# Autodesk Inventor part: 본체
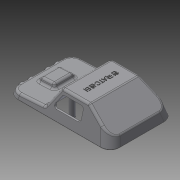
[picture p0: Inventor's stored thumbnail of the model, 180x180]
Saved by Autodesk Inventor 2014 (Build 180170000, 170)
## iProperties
Created: 2015-05
Part Number: 본체
Material: 일반
Document SubType Name: Modeling
Designer: 학생용
Density: 1 g/cm^3
Appearance: 기본값
Author: 학생용
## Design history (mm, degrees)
sketch "스케치1"
  geometry: L1 (0, 0)-(-122, 0); L2 (-122, 0)-(-120.392, 6); L3 (-120.392, 6)-(-80, 8.117); L4 (-80, 8.117)-(-65.701, 31); L5 (-65.701, 31)-(-32.947, 31); L6 (-32.947, 31)-(-2.947, 11); L7 (-2.947, 11)-(0, 0); 1 further point
  constraints: 14 end point, 2 horizontal, 1 coincident
  dimensions: "d0" = 122 distance of L1.start L1.end; "d1" = 105 deg angle of L2 L1; "d2" = 105 deg angle of L1 L7; "d3" = 125 deg angle of L4 L3; "d4" = 6 vertical distance of L1.end L2.end; "d5" = 31 distance from line of L1 L5.end; "d6" = 30 horizontal distance of L6.end L5.end; "d7" = 42 horizontal distance of L1.end L3.end; "d8" = 20 vertical distance of L6.end L5.end; "d9" = 3 deg angle of L1 L3
extrude "돌출1" new body sketch "스케치1" distance "d10" = 76; taper "d11" = 0 deg
node "작업 평면1"
sketch "스케치3"
  geometry: L1 (0, 0)-(6, 0) reference; L2 (6, 0)-(6, -76) reference; L3 (0, -76)-(6, -76) reference; L4 (0, 0)-(0, -76) reference; L5 (37.372, -76)-(37.372, -65.986); L6 (37.372, -65.986)-(0, -76); L7 (0, -76)-(37.372, -76); L8 (0, 0)-(37.372, -10.014); L9 (0, 0)-(37.372, 0); L10 (37.372, 0)-(37.372, -10.014); 1 further point
  constraints: 12 end point, 2 horizontal, 1 coincident, 1 parallel, 1 vertical, 1 vertical alignment
  dimensions: "d15" = 105 deg angle of L4 L8; "d16" = 105 deg angle of L6 L4; "d17" = 31.37205 distance between parallel lines of L5 L2
extrude "돌출2" cut sketch "스케치3" stored distance "d18" = 76; taper "d19" = 0 deg
sketch "스케치4"
  geometry: L1 (0, 0)-(0, 72.785) reference; L2 (9.08, 49.392)-(29.08, 49.392); L3 (29.08, 49.392)-(29.08, 23.392); L4 (29.08, 23.392)-(9.08, 23.392); L5 (9.08, 23.392)-(9.08, 49.392); L6 (9.08, 49.392)-(29.08, 23.392); L7 (29.08, 49.392)-(9.08, 23.392); L8 (-1.92, -1.608)-(-1.92, 74.392) reference; 4 further points
  constraints: 12 end point, 4 midpoint, 2 parallel, 1 horizontal, 1 horizontal alignment, 1 perpendicular
  dimensions: "d20" = 20 distance of L2.start L2.end; "d21" = 26 distance of L2.end L3.end; "d22" = 11 distance between parallel lines of L5 L8
extrude "돌출3" join sketch "스케치4" distance "d23" = 5; taper "d24" = -20 deg
fillet "모깎기1" dims "d25" = 12
fillet "모깎기2" dims "d26" = 12
feature "쉘1" dims "d28" = 2
node "작업 평면2"
sketch "스케치5"
  geometry: L1 (-72.303, 11)-(-38.303, 11); L2 (-38.303, 11)-(-38.303, 26); L3 (-38.303, 26)-(-62.929, 26); L4 (-62.929, 26)-(-72.303, 11); L5 (-33.856, 31)-(-64.038, 31) reference; L6 (-66.582, 29.59)-(-79.172, 9.441) reference; L7 (-14.472, 18.683)-(-32.192, 30.496) reference; 1 further point
  constraints: 8 end point, 2 horizontal, 1 parallel, 1 vertical
  dimensions: "d32" = 34 distance of L1.start L1.end; "d33" = 15 distance between parallel lines of L1 L3; "d34" = 5 distance between parallel lines of L3 L5; "d36" = 5 distance from line of L6 L3.end
extrude "돌출4" cut sketch "스케치5" stored distance "d40" = 5; taper "d41" = 0 deg
fillet "모깎기4" dims "d42" = 3
sketch "스케치8" dims "d55" = 6
  geometry: L1 (12.179, 38.008)-(12.179, 14.809) reference; L2 (12.179, 38.008)-(12.179, 26.409); L3 (29.355, 14.809)-(29.355, 38.008) reference; L4 (12.179, 26.409)-(29.355, 26.409); L5 (100.767, 23.409)-(124.378, 23.409); L6 (29.355, 26.409)-(20.767, 26.409); C1 r 3 at (20.767, 26.409); C2 r 3 at (60.767, 4.409); C3 r 3 at (60.767, 48.409); 4 further points
  constraints: 8 end point, 5 midpoint, 3 centre point, 3 horizontal, 2 vertical alignment, 1 coincident, 1 horizontal alignment, 1 vertical, 2 other
  dimensions: "d52" = 6 diameter of C1; "d53" = 6 diameter of C2; "d54" = 6 diameter of C3; "d57" = 11.5995 distance of L1.start L2.end; "d58" = 8.588 distance of L6.start L6.end; "d59" = 80 distance of point (100.767, 26.409) C1.centre; "d60" = 40 horizontal distance of C2.centre L6.end; "d61" = 22 vertical distance of C2.centre L6.end; "d62" = 44 distance of C2.centre C3.centre
fillet "모깎기5" dims "d56" = 3
extrude "돌출5" join sketch "스케치8" stored distance "d63" = 5; taper "d64" = 0 deg
node "작업 평면3"
sketch "스케치9"
  geometry: L1 (-109.821, 4.551)-(-118.837, 4.079) reference; L2 (-118.837, 4.079)-(-119.929, 0) reference; L3 (-119.929, 0)-(-122, 0) reference; L4 (-122, 0)-(-120.956, 3.895) reference; L5 (-118.216, 6.114)-(-113.422, 6.365) reference; L6 (-110.71, 8.484)-(-110.383, 9.555) reference; L7 (-107.671, 11.674)-(-95.528, 12.31) reference; L8 (-92.61, 10.486)-(-92.172, 9.456) reference; L9 (-89.254, 7.632)-(-81.56, 8.035) reference; L10 (-79.172, 9.441)-(-66.582, 29.59) reference; L11 (-64.038, 31)-(-33.856, 31) reference; L12 (-32.192, 30.496)-(-3.888, 11.627) reference; L13 (-2.655, 9.908)-(0, 0) reference; L14 (0, 0)-(-2.071, 0) reference; L15 (-2.071, 0)-(-4.684, 9.754) reference; L16 (-4.684, 9.754)-(-18.233, 18.787) reference; L17 (-18.233, 18.787)-(-18.233, 0) reference; L18 (-18.233, 0)-(-24.233, 0) reference; L19 (-24.233, 0)-(-24.233, 22.787) reference; L20 (-24.233, 22.787)-(-33.553, 29) reference; L21 (-33.553, 29)-(-64.592, 29) reference; L22 (-64.592, 29)-(-78.856, 6.174) reference; L23 (-78.856, 6.174)-(-92.645, 5.451) reference; L24 (-92.645, 5.451)-(-94.725, 10.349) reference; L25 (-94.725, 10.349)-(-98.233, 10.165) reference; L26 (-98.233, 10.165)-(-98.233, 0) reference; L27 (-98.233, 0)-(-104.233, 0) reference; L28 (-104.233, 0)-(-104.233, 9.851) reference; L29 (-104.233, 9.851)-(-108.265, 9.64) reference; L30 (-108.265, 9.64)-(-109.821, 4.551) reference; L31 (-106.233, 2)-(-96.233, 2); L32 (-107.587, 9.675)-(-106.233, 2); L33 (-94.761, 10.347)-(-96.233, 2); L34 (-107.587, 9.675)-(-104.233, 9.851); L35 (-94.725, 10.349)-(-107.587, 9.675); L36 (-26.233, 2)-(-16.233, 2); A1 r 3 centre (-118.059, 3.118) between (-118.216, 6.114) and (-120.956, 3.895) reference; A2 r 3 centre (-113.579, 9.361) between (-113.422, 6.365) and (-110.71, 8.484) reference; A3 r 3 centre (-107.514, 8.678) between (-107.671, 11.674) and (-110.383, 9.555) reference; A4 r 3 centre (-95.371, 9.314) between (-92.61, 10.486) and (-95.528, 12.31) reference; A5 r 3 centre (-89.411, 10.628) between (-92.172, 9.456) and (-89.254, 7.632) reference; A6 r 3 centre (-81.717, 11.031) between (-81.56, 8.035) and (-79.172, 9.441) reference; A7 r 3 centre (-64.038, 28) between (-64.038, 31) and (-66.582, 29.59) reference; A8 r 3 centre (-33.856, 28) between (-32.192, 30.496) and (-33.856, 31) reference; A9 r 3 centre (-5.553, 9.131) between (-2.655, 9.908) and (-3.888, 11.627) reference; 6 further points
  constraints: 12 end point, 4 midpoint, 4 vertical alignment, 2 horizontal, 2 point on line
  dimensions: "d66" = 10 distance of L31.end L31.start; "d67" = 2 distance between parallel lines of L27 L31; "d68" = 20 deg angle of L33 L32; "d69" = 80 deg angle of L14 L33; "d70" = 11.03446 distance from line of point (-101.233, 11.034) L14; "d71" = 10 distance of L36.start L36.end; "d73" = 2 distance between parallel lines of L18 L36
extrude "돌출6" join sketch "스케치9" stored distance "d78" = 2; taper "d79" = 0 deg
sketch "스케치10"
  geometry: L1 (-109.821, 4.551)-(-118.837, 4.079) reference; L2 (-118.837, 4.079)-(-119.929, 0) reference; L3 (-119.929, 0)-(-122, 0) reference; L4 (-122, 0)-(-120.956, 3.895) reference; L5 (-118.216, 6.114)-(-113.422, 6.365) reference; L6 (-110.71, 8.484)-(-110.383, 9.555) reference; L7 (-107.671, 11.674)-(-95.528, 12.31) reference; L8 (-92.61, 10.486)-(-92.172, 9.456) reference; L9 (-89.254, 7.632)-(-81.56, 8.035) reference; L10 (-79.172, 9.441)-(-66.582, 29.59) reference; L11 (-64.038, 31)-(-33.856, 31) reference; L12 (-32.192, 30.496)-(-3.888, 11.627) reference; L13 (-2.655, 9.908)-(0, 0) reference; L14 (0, 0)-(-2.071, 0) reference; L15 (-2.071, 0)-(-4.684, 9.754) reference; L16 (-4.684, 9.754)-(-18.233, 18.787) reference; L17 (-18.233, 18.787)-(-18.233, 0) reference; L18 (-18.233, 0)-(-24.233, 0) reference; L19 (-24.233, 0)-(-24.233, 22.787) reference; L20 (-24.233, 22.787)-(-33.553, 29) reference; L21 (-33.553, 29)-(-64.592, 29) reference; L22 (-64.592, 29)-(-78.856, 6.174) reference; L23 (-78.856, 6.174)-(-92.645, 5.451) reference; L24 (-92.645, 5.451)-(-94.725, 10.349) reference; L25 (-94.725, 10.349)-(-94.761, 10.347) reference; L26 (-94.761, 10.347)-(-96.233, 2) reference; L27 (-96.233, 2)-(-98.233, 2) reference; L28 (-98.233, 2)-(-98.233, 0) reference; L29 (-98.233, 0)-(-104.233, 0) reference; L30 (-104.233, 0)-(-104.233, 2) reference; L31 (-104.233, 2)-(-106.233, 2) reference; L32 (-106.233, 2)-(-107.587, 9.675) reference; L33 (-107.587, 9.675)-(-108.265, 9.64) reference; L34 (-108.265, 9.64)-(-109.821, 4.551) reference; L35 (-26.233, 2)-(-16.233, 2); L36 (-16.233, 2)-(-13.795, 15.828); L37 (-26.233, 2)-(-30.653, 27.067); L38 (-30.653, 27.067)-(-13.795, 15.828); A1 r 3 centre (-118.059, 3.118) between (-118.216, 6.114) and (-120.956, 3.895) reference; A2 r 3 centre (-113.579, 9.361) between (-113.422, 6.365) and (-110.71, 8.484) reference; A3 r 3 centre (-107.514, 8.678) between (-107.671, 11.674) and (-110.383, 9.555) reference; A4 r 3 centre (-95.371, 9.314) between (-92.61, 10.486) and (-95.528, 12.31) reference; A5 r 3 centre (-89.411, 10.628) between (-92.172, 9.456) and (-89.254, 7.632) reference; A6 r 3 centre (-81.717, 11.031) between (-81.56, 8.035) and (-79.172, 9.441) reference; A7 r 3 centre (-64.038, 28) between (-64.038, 31) and (-66.582, 29.59) reference; A8 r 3 centre (-33.856, 28) between (-32.192, 30.496) and (-33.856, 31) reference; A9 r 3 centre (-5.553, 9.131) between (-2.655, 9.908) and (-3.888, 11.627) reference; 4 further points
  constraints: 8 end point, 4 point on line, 2 midpoint, 1 horizontal, 1 horizontal alignment, 1 vertical alignment
  dimensions: "d80" = 10 distance of L35.start L35.end; "d81" = 2 distance between parallel lines of L18 L35; "d83" = 20 deg angle of L37 L36; "d84" = 80 deg angle of L35 L36
extrude "돌출7" join sketch "스케치10" stored distance "d85" = 2; taper "d86" = 0 deg
hole "구멍1" diameter "d89" = 3.242; stored, may be unused: countersink angle "d93" = 90 deg, drill point angle "d95" = 118 deg; dims "d87" = 10, "d88" = 10, "d90" = 9, "d91" = 4, "d92" = 2, "d94" = 11
hole "구멍2" diameter "d98" = 3.242; stored, may be unused: countersink angle "d102" = 90 deg, drill point angle "d104" = 118 deg; dims "d96" = 10, "d97" = 10, "d99" = 9, "d100" = 4, "d101" = 2, "d103" = 11
node "작업 평면4"
sketch "스케치11"
  geometry: L1 (0, -48)-(0, -28); A1 r 4 centre (0, -59) between (0, -63) and (0, -55); A2 r 4 centre (0, -48) between (0, -52) and (0, -44); A3 r 4 centre (0, -28) between (0, -32) and (0, -24); A4 r 4 centre (0, -17) between (0, -21) and (0, -13); 4 further points
  constraints: 8 point on circle, 4 centre point, 3 equal radius, 3 vertical alignment, 2 coincident, 2 end point, 1 midpoint, 10 other
  dimensions: "d106" = 8 diameter of A1; "d107" = 11 distance of A2.centre A1.centre; "d108" = 11 distance of A4.centre A3.centre; "d109" = 20 distance of A2.centre A3.centre
extrude "돌출8" join sketch "스케치11" stored distance "d111" = 0; taper "d112" = 0 deg
chamfer "모따기1" distance "d113" = 1; stored, may be unused: second distance "d114" = 2, angle "d115" = 45 deg
sketch "스케치12"
  geometry: L1 (-12.591, 13)-(-13.591, 14) reference; L2 (-12.591, 13)-(-11.591, 13) reference; L3 (-11.591, 13)-(-11.591, 11.591) reference; L4 (98.818, 0)-(0, 0) reference; L5 (110.409, 64.409)-(110.409, 11.591) reference; L6 (98.818, 76)-(0, 76) reference; L7 (-11.591, 64.409)-(-11.591, 63) reference; L8 (-12.591, 63)-(-11.591, 63) reference; L9 (-13.591, 62)-(-12.591, 63) reference; L10 (-13.591, 62)-(-13.591, 56) reference; L11 (-12.591, 55)-(-13.591, 56) reference; L12 (-12.591, 55)-(-11.591, 55) reference; L13 (-11.591, 55)-(-11.591, 52) reference; L14 (-12.591, 52)-(-11.591, 52) reference; L15 (-13.591, 51)-(-12.591, 52) reference; L16 (-13.591, 51)-(-13.591, 45) reference; L17 (-12.591, 44)-(-13.591, 45) reference; L18 (-12.591, 44)-(-11.591, 44) reference; L19 (-11.591, 44)-(-11.591, 32) reference; L20 (-12.591, 32)-(-11.591, 32) reference; L21 (-13.591, 31)-(-12.591, 32) reference; L22 (-13.591, 31)-(-13.591, 25) reference; L23 (-12.591, 24)-(-13.591, 25) reference; L24 (-12.591, 24)-(-11.591, 24) reference; L25 (-11.591, 24)-(-11.591, 21) reference; L26 (-12.591, 21)-(-11.591, 21) reference; L27 (-13.591, 20)-(-12.591, 21) reference; L28 (-13.591, 20)-(-13.591, 14) reference; L29 (0, 75)-(98.818, 75); L30 (109.409, 64.409)-(109.409, 11.591); L31 (98.818, 1)-(0, 1); L32 (-10.591, 11.591)-(-10.591, 14); L33 (-10.591, 14)-(-12.177, 14); L34 (-12.177, 14)-(-12.591, 14.414); L35 (-12.591, 14.414)-(-12.591, 19.586); L36 (-12.591, 19.586)-(-12.177, 20); L37 (-12.177, 20)-(-10.591, 20); L38 (-10.591, 20)-(-10.591, 25); L39 (-10.591, 25)-(-12.177, 25); L40 (-12.177, 25)-(-12.591, 25.414); L41 (-12.591, 25.414)-(-12.591, 30.586); L42 (-12.591, 30.586)-(-12.177, 31); L43 (-12.177, 31)-(-10.591, 31); L44 (-10.591, 31)-(-10.591, 45); L45 (-10.591, 45)-(-12.177, 45); L46 (-12.177, 45)-(-12.591, 45.414); L47 (-12.591, 45.414)-(-12.591, 50.586); L48 (-12.591, 50.586)-(-12.177, 51); L49 (-12.177, 51)-(-10.591, 51); L50 (-10.591, 51)-(-10.591, 56); L51 (-10.591, 56)-(-12.177, 56); L52 (-12.177, 56)-(-12.591, 56.414); L53 (-12.591, 56.414)-(-12.591, 61.586); L54 (-12.591, 61.586)-(-12.177, 62); L55 (-12.177, 62)-(-10.591, 62); L56 (-10.591, 62)-(-10.591, 64.409); 5 further points; 4 other entities
  constraints: 56 end point, 7 parallel, 40 other
  dimensions: "d116" = 1 distance between parallel lines of L29 L6
extrude "돌출9" cut sketch "스케치12" distance "d117" = 1; taper "d118" = 0 deg
sketch "스케치13"
  geometry: L1 (0, 0)-(0, 54.783) reference; L2 (0, 54.783)-(30.182, 54.783) reference; 4 further points
  constraints: 2 midpoint, 1 horizontal alignment, 1 vertical alignment, 1 other
feature "엠보싱1" sketch "스케치13" dims "d0" = 122, "d1" = 105 deg, "d2" = 105 deg, "d3" = 125 deg, "d4" = 6, "d5" = 31, "d6" = 30, "d7" = 42, "d8" = 20, "d9" = 3 deg, "d17" = 31.37205, "d119" = 0.5, "d120" = 0
hole "구멍3" diameter "d123" = 3.242; stored, may be unused: countersink angle "d127" = 90 deg, drill point angle "d129" = 118 deg; dims "d121" = 10, "d122" = 10, "d124" = 9, "d125" = 4, "d126" = 2, "d128" = 11
hole "구멍4" diameter "d132" = 3.242; stored, may be unused: countersink angle "d136" = 90 deg, drill point angle "d138" = 118 deg; dims "d130" = 10, "d131" = 10, "d133" = 9, "d134" = 4, "d135" = 2, "d137" = 11
node "솔리드1"
node "투영된 루프1"
node "절단 모서리 투영1"
node "절단 모서리 투영2"
other parameters: "d14" = -133, "d29" = 5.5, "d65" = -38, "d105" = -124
